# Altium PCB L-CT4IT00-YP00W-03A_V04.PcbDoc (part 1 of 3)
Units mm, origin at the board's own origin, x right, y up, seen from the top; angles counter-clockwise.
Board outline 52 x 31.8 mm, 4 copper layers (Top Layer, Layer 1, Layer 2, Bottom Layer), stack 1.288 mm thick; 160 components, 112 nets, 631 pads, 1087 vias.
Unrouted connection lines stored in the file: 130.
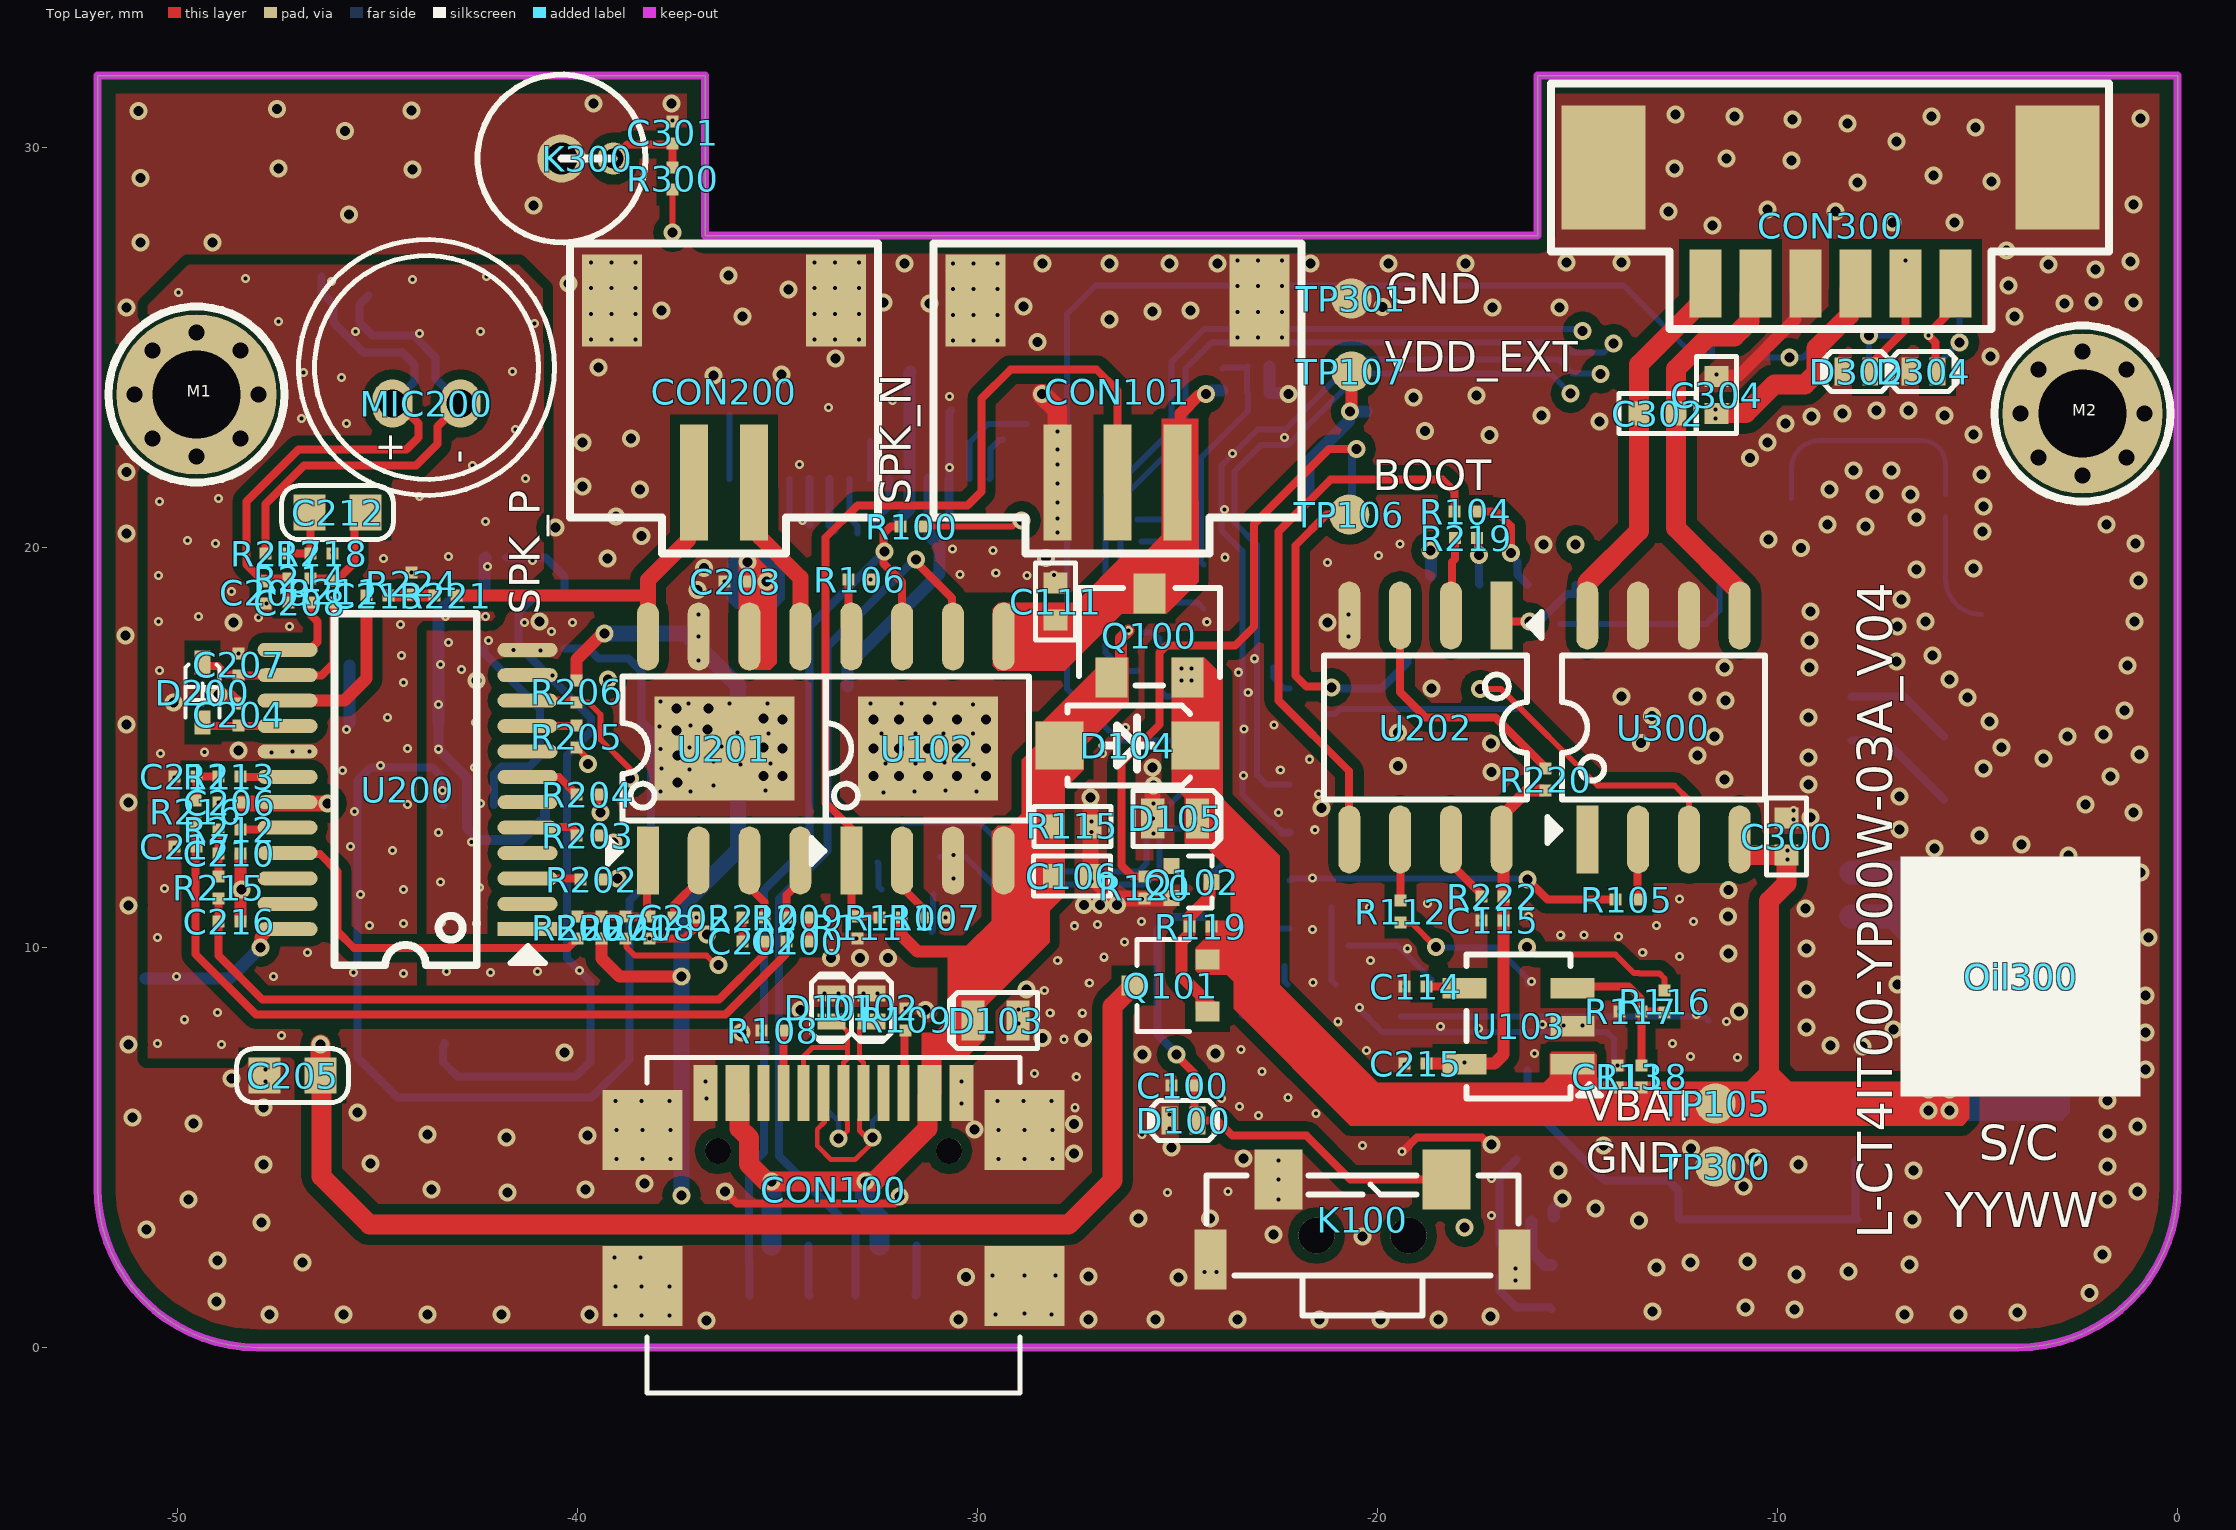
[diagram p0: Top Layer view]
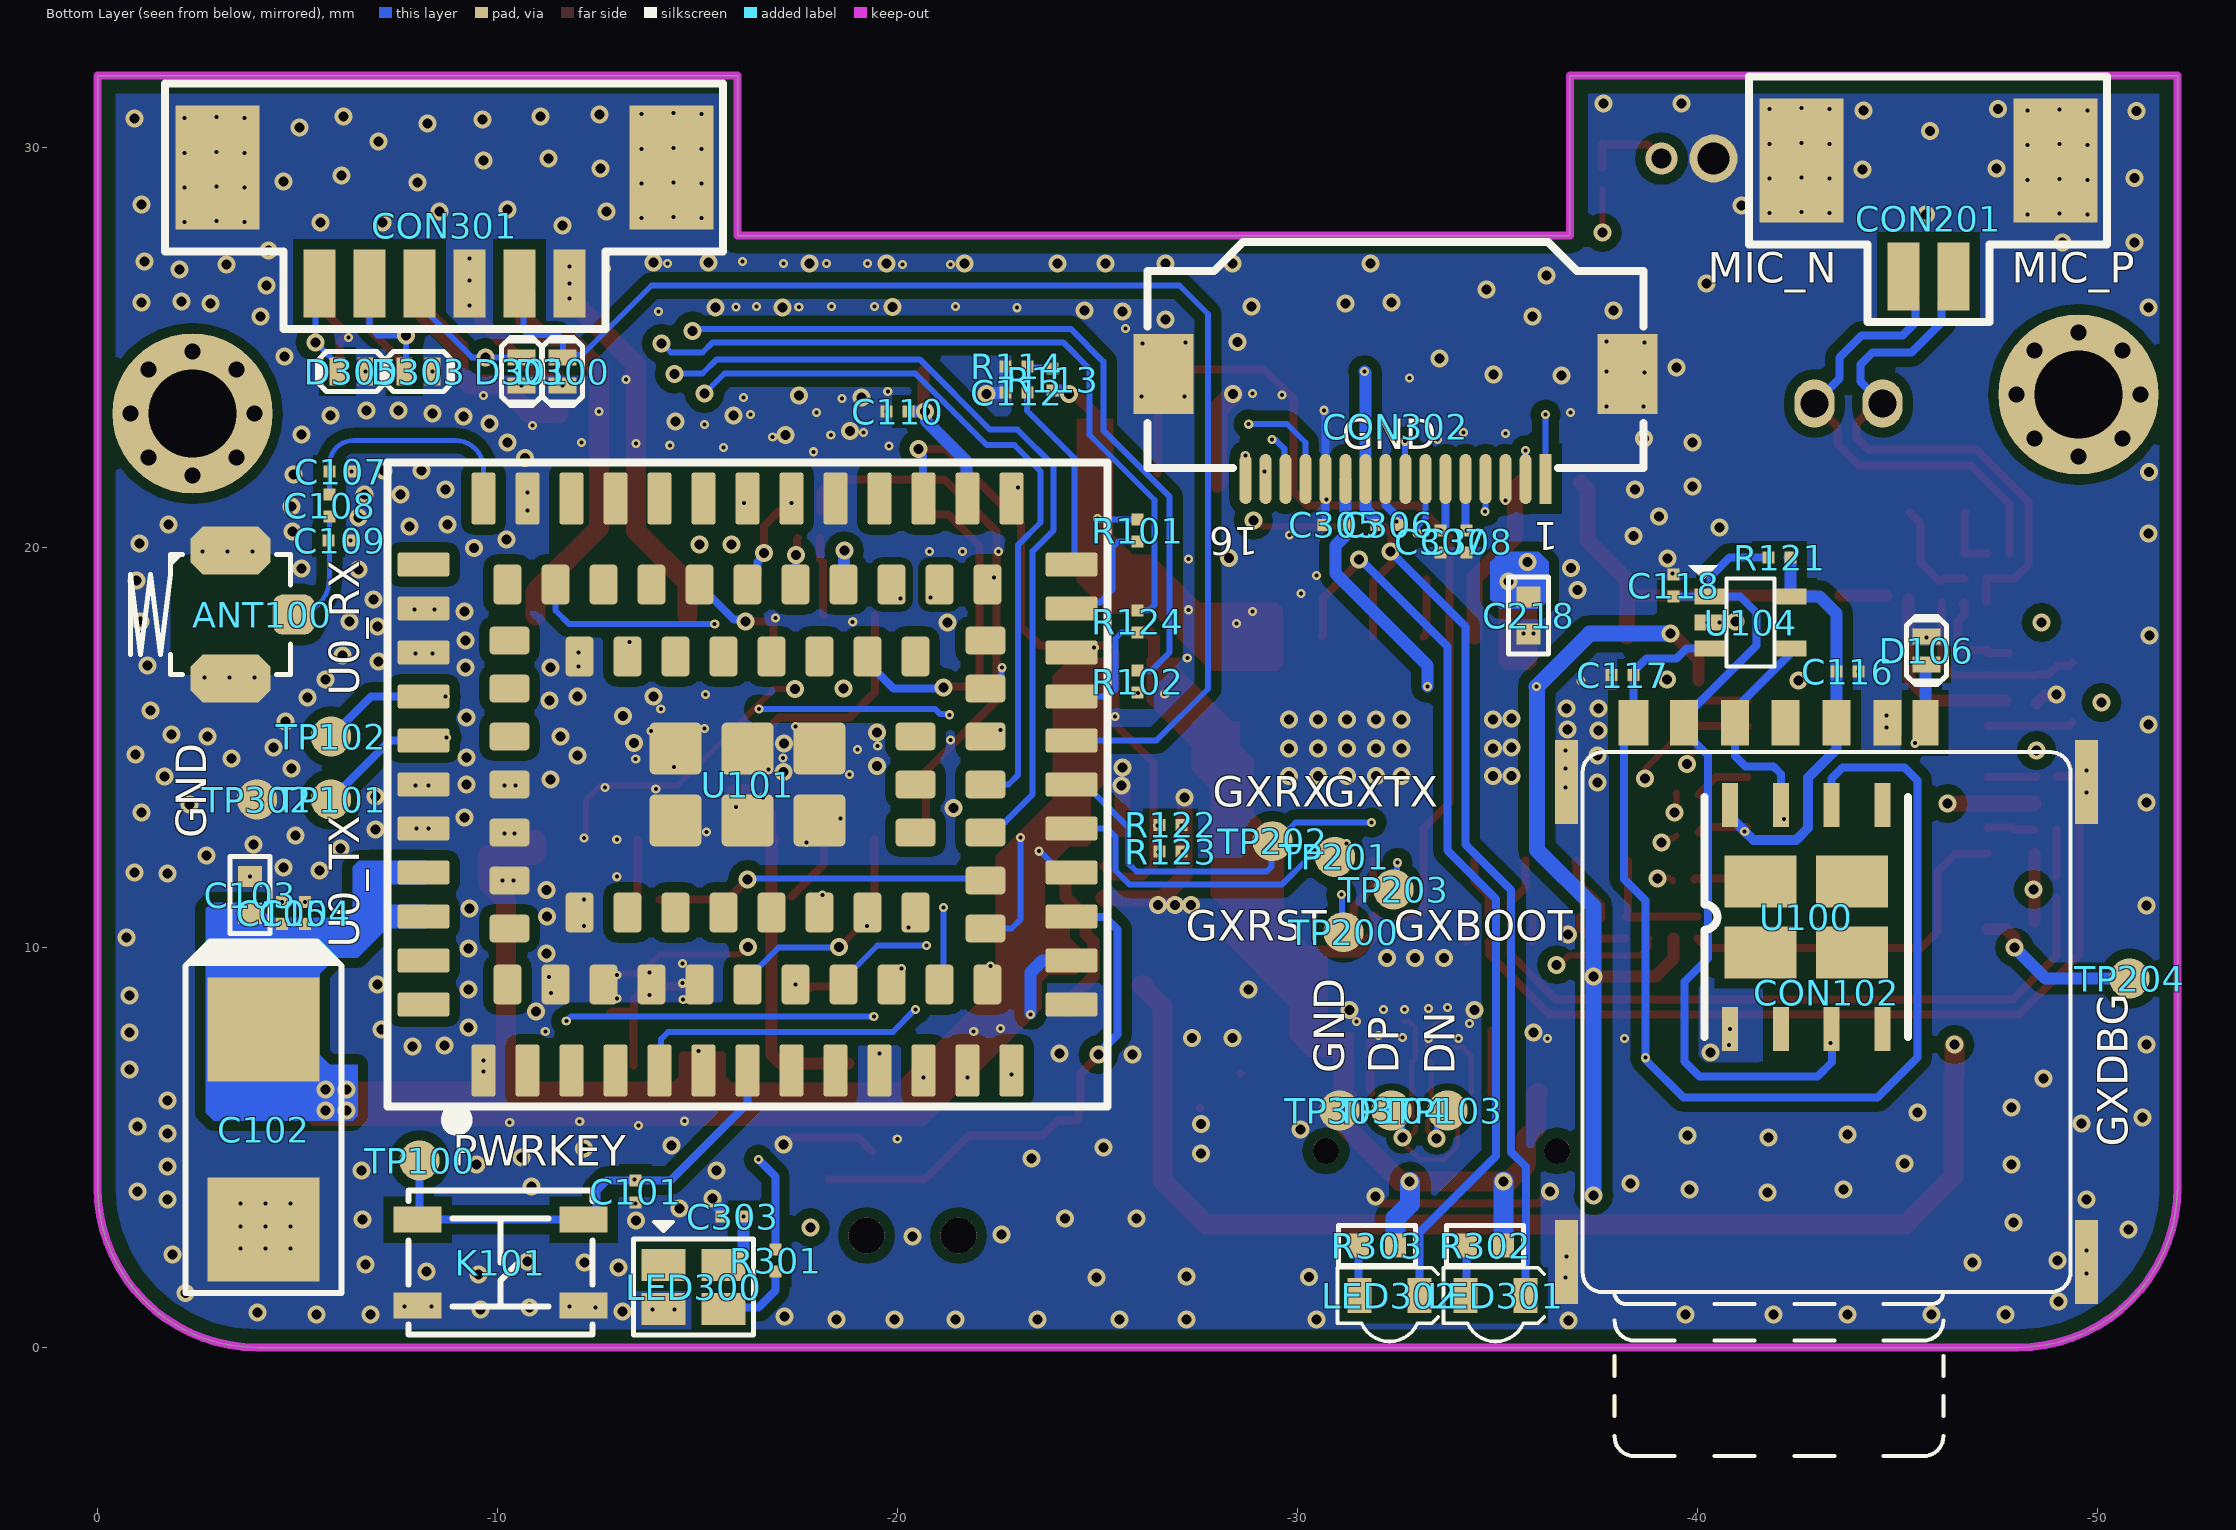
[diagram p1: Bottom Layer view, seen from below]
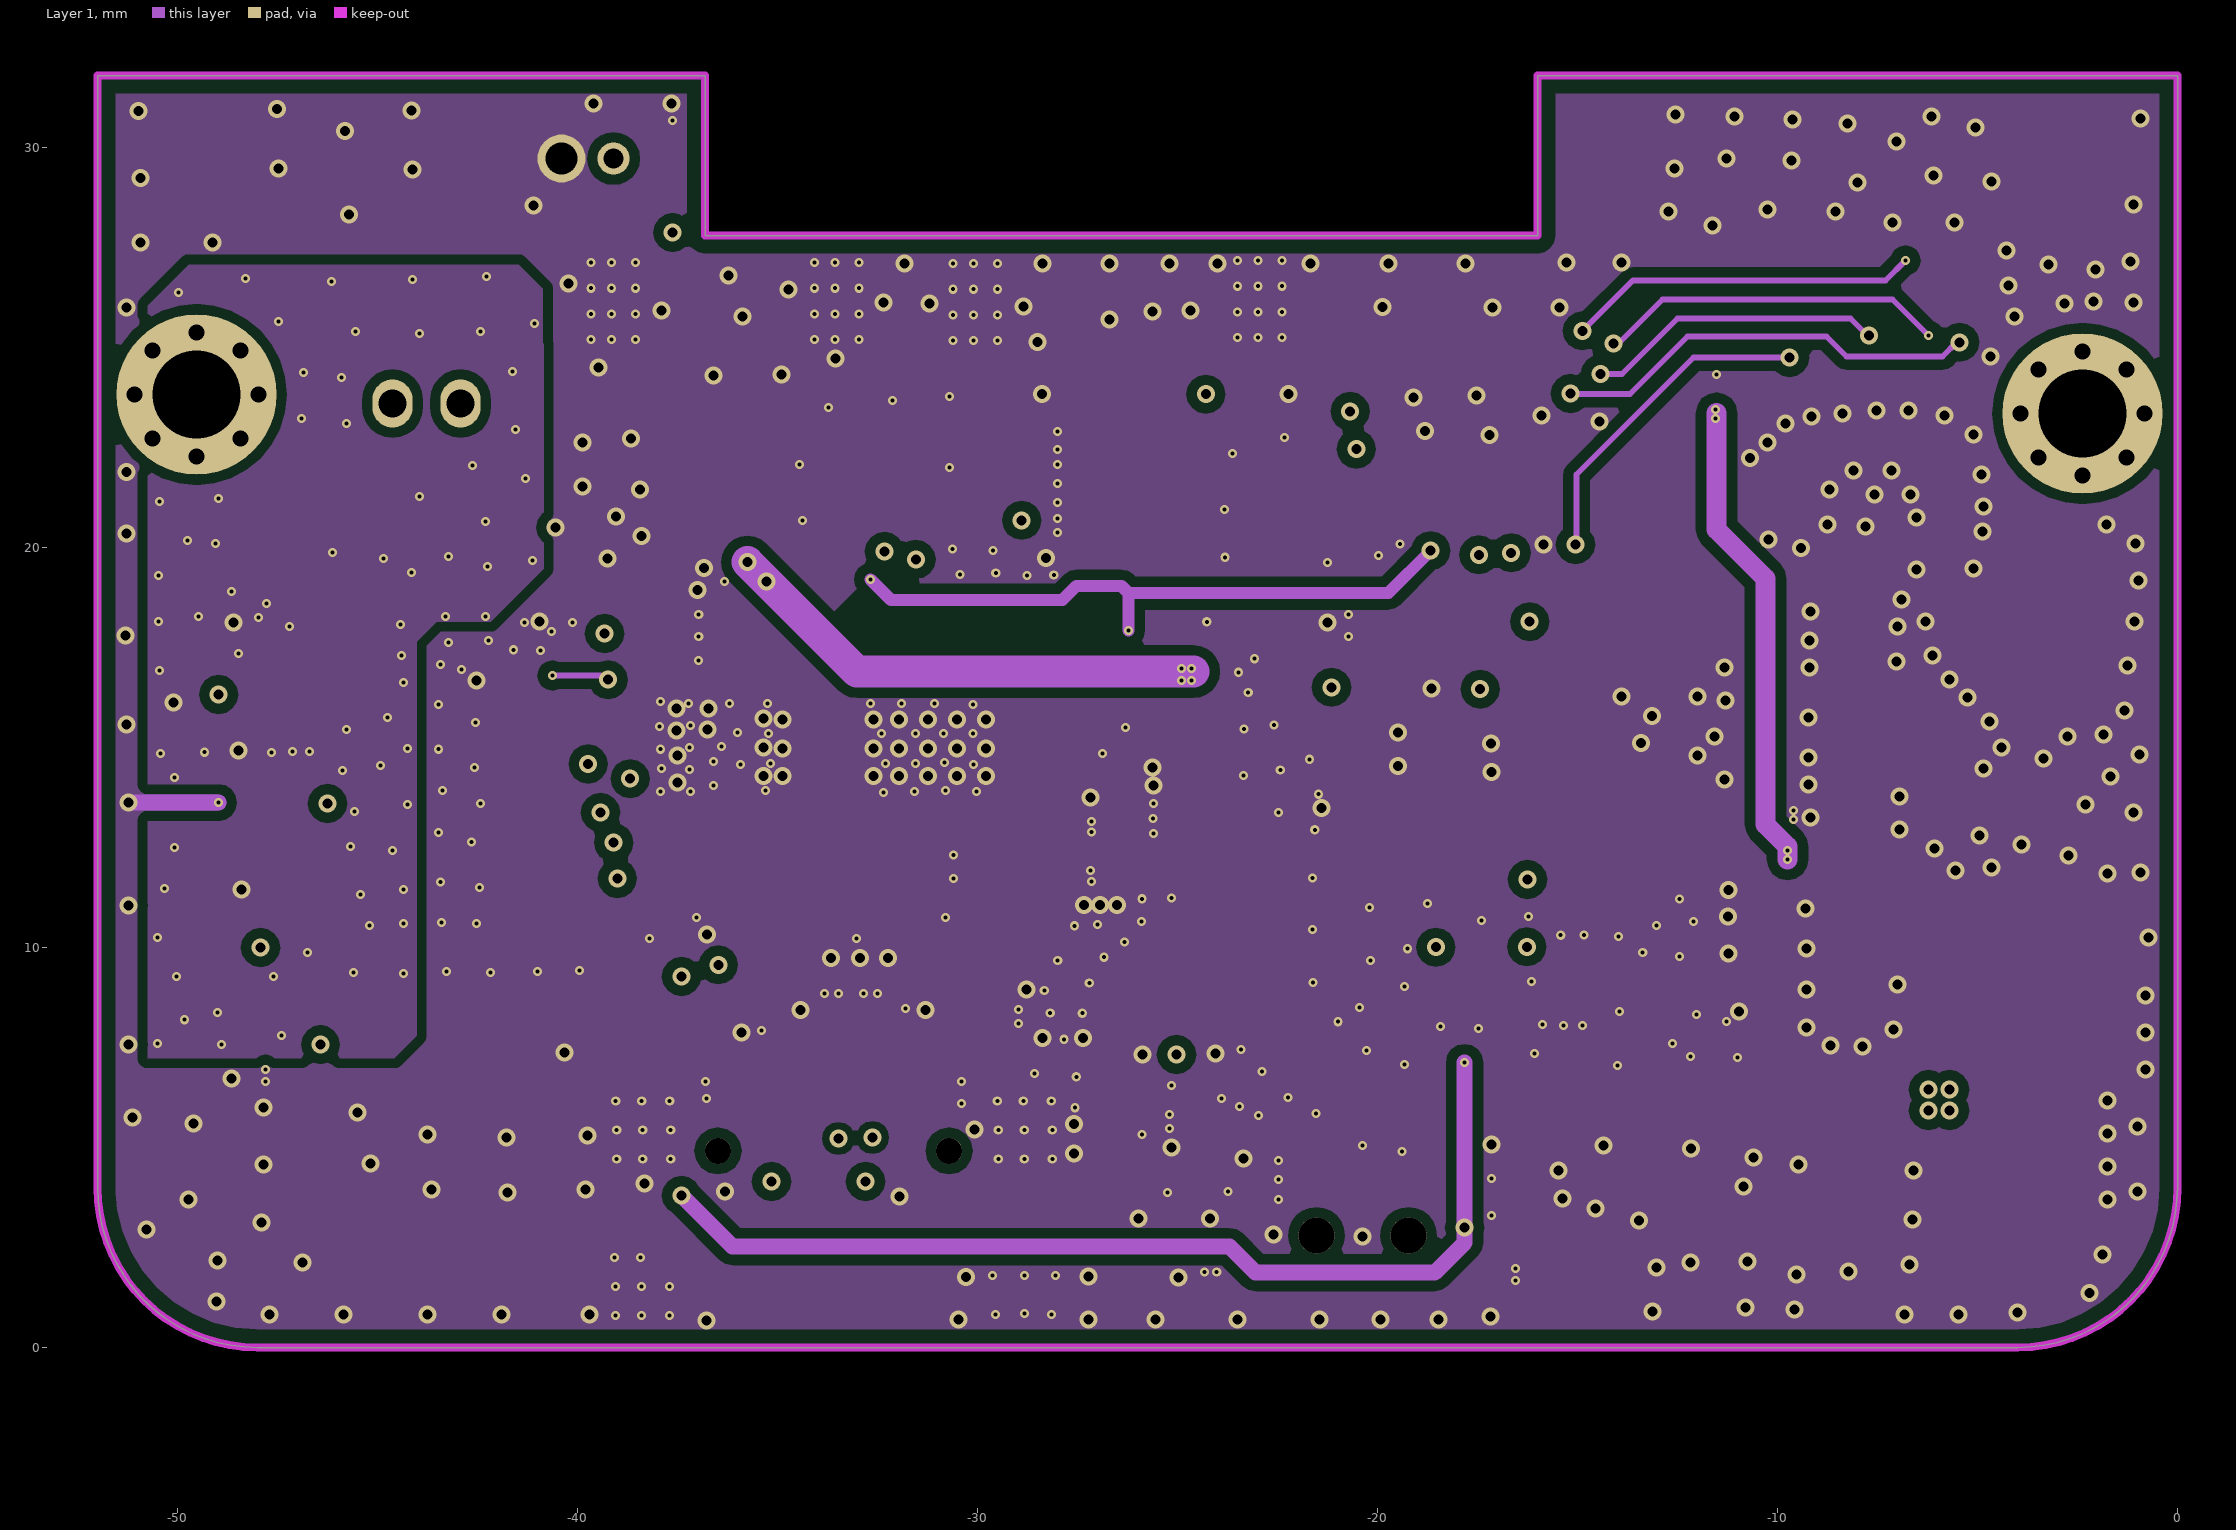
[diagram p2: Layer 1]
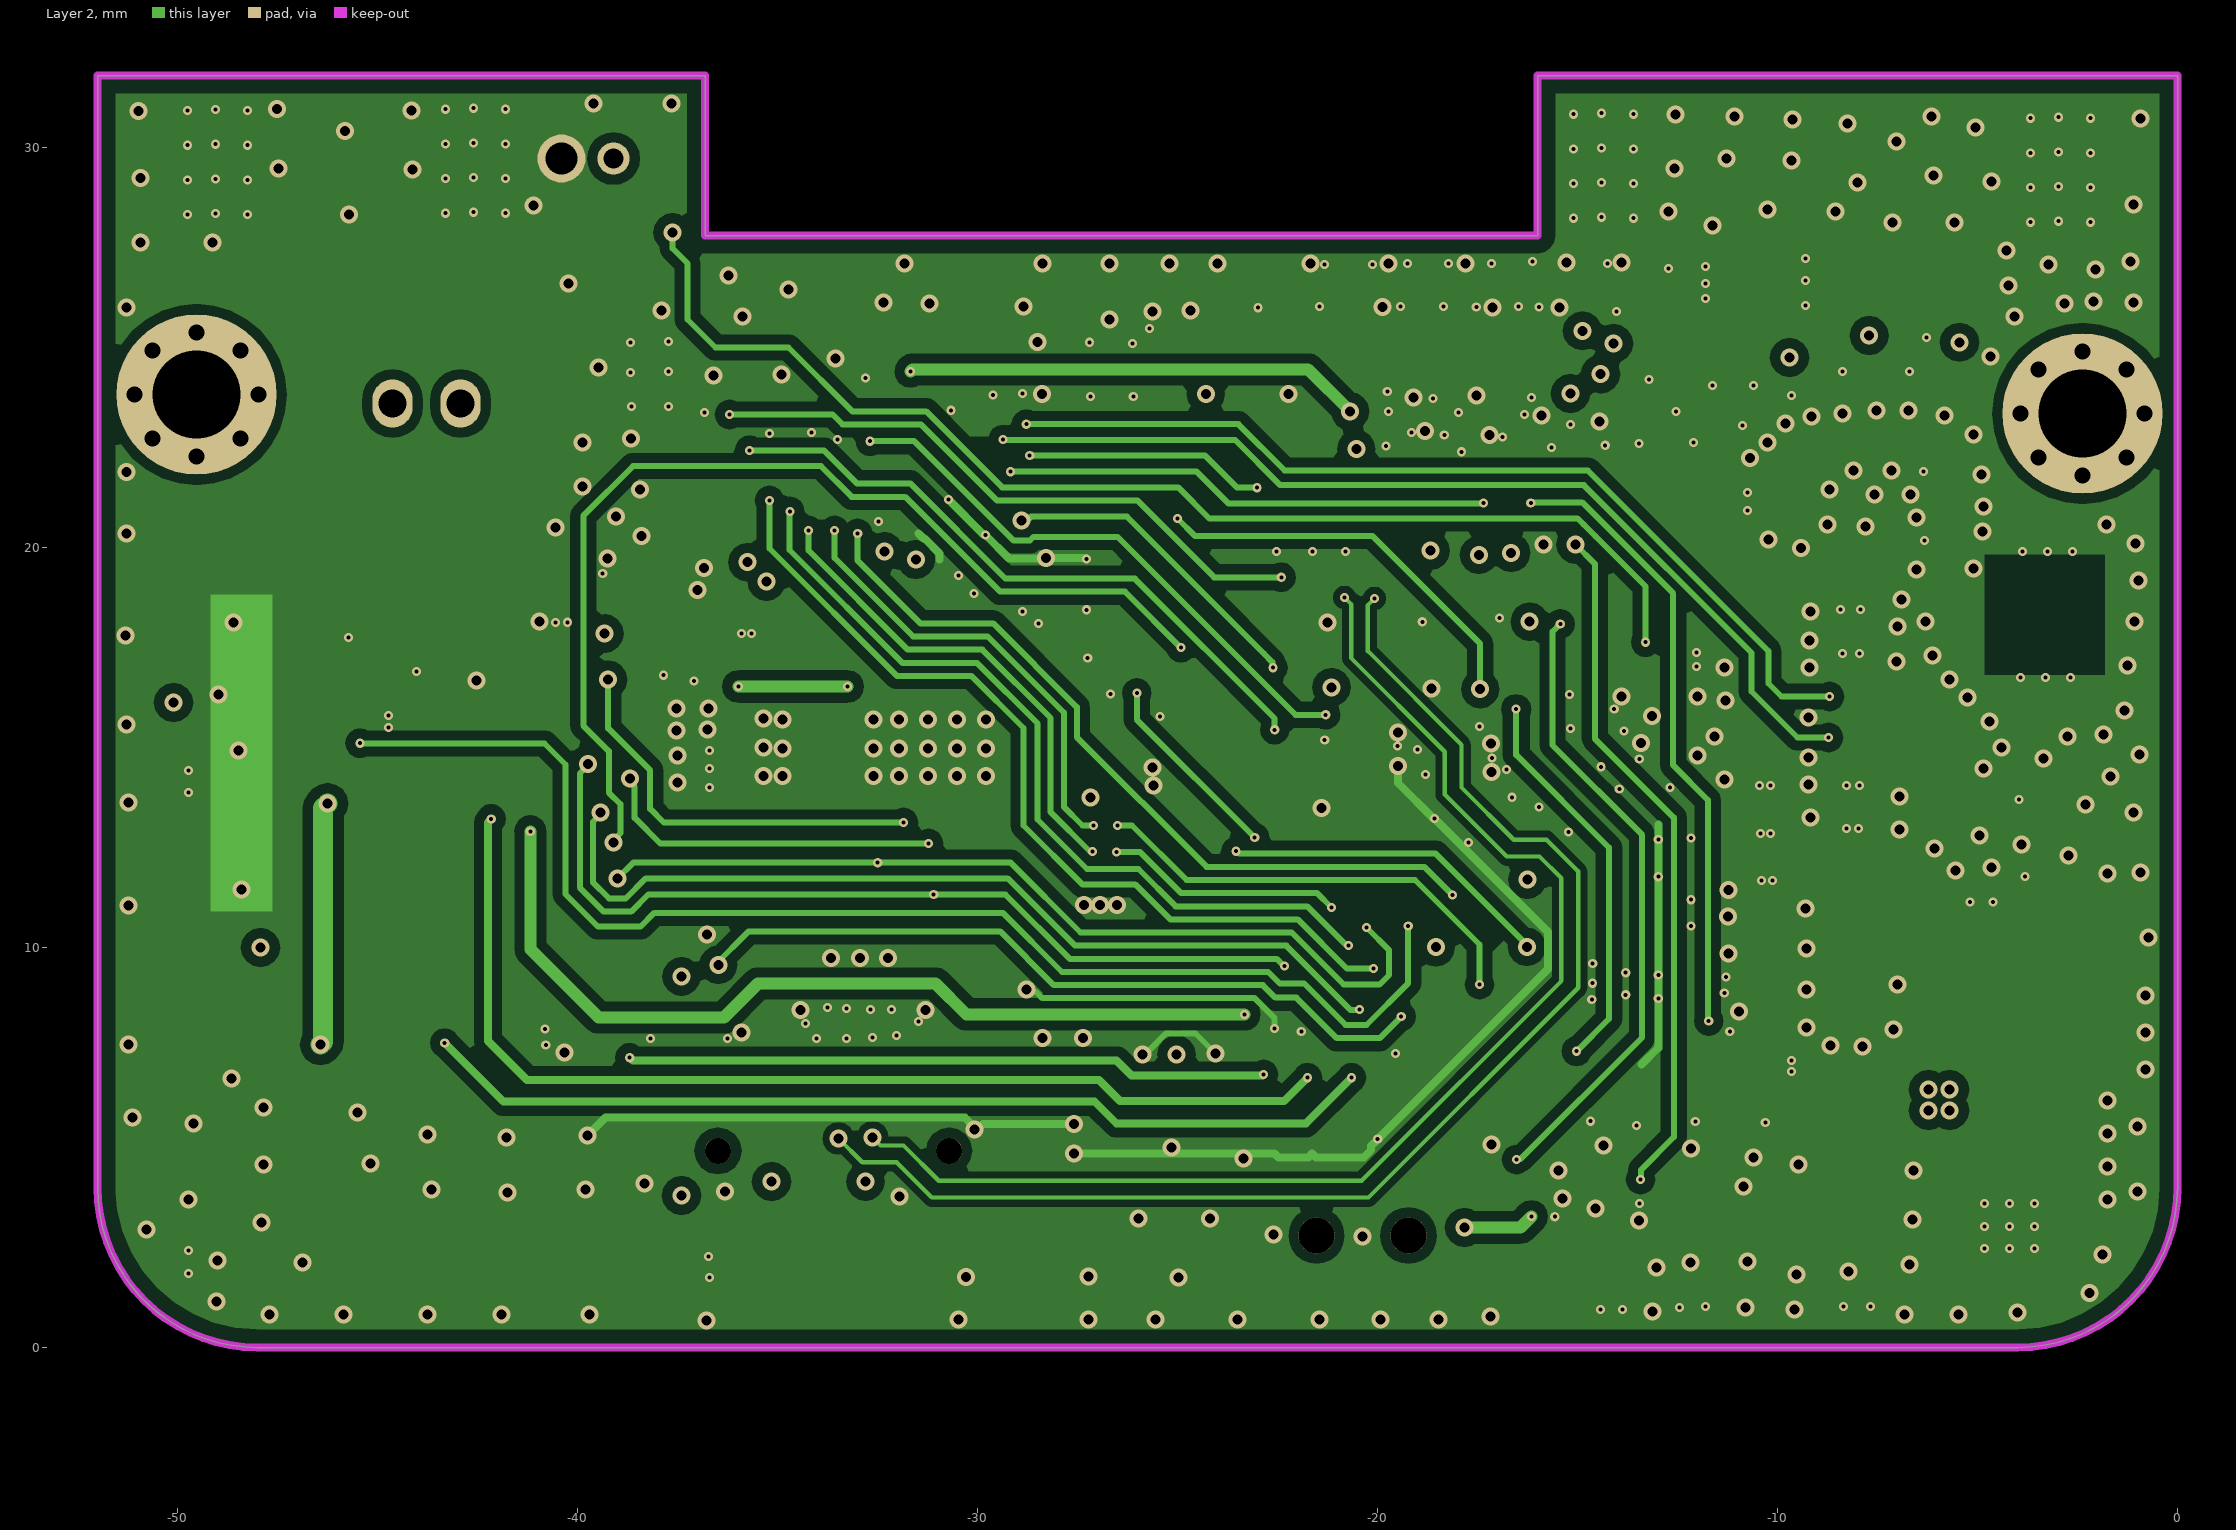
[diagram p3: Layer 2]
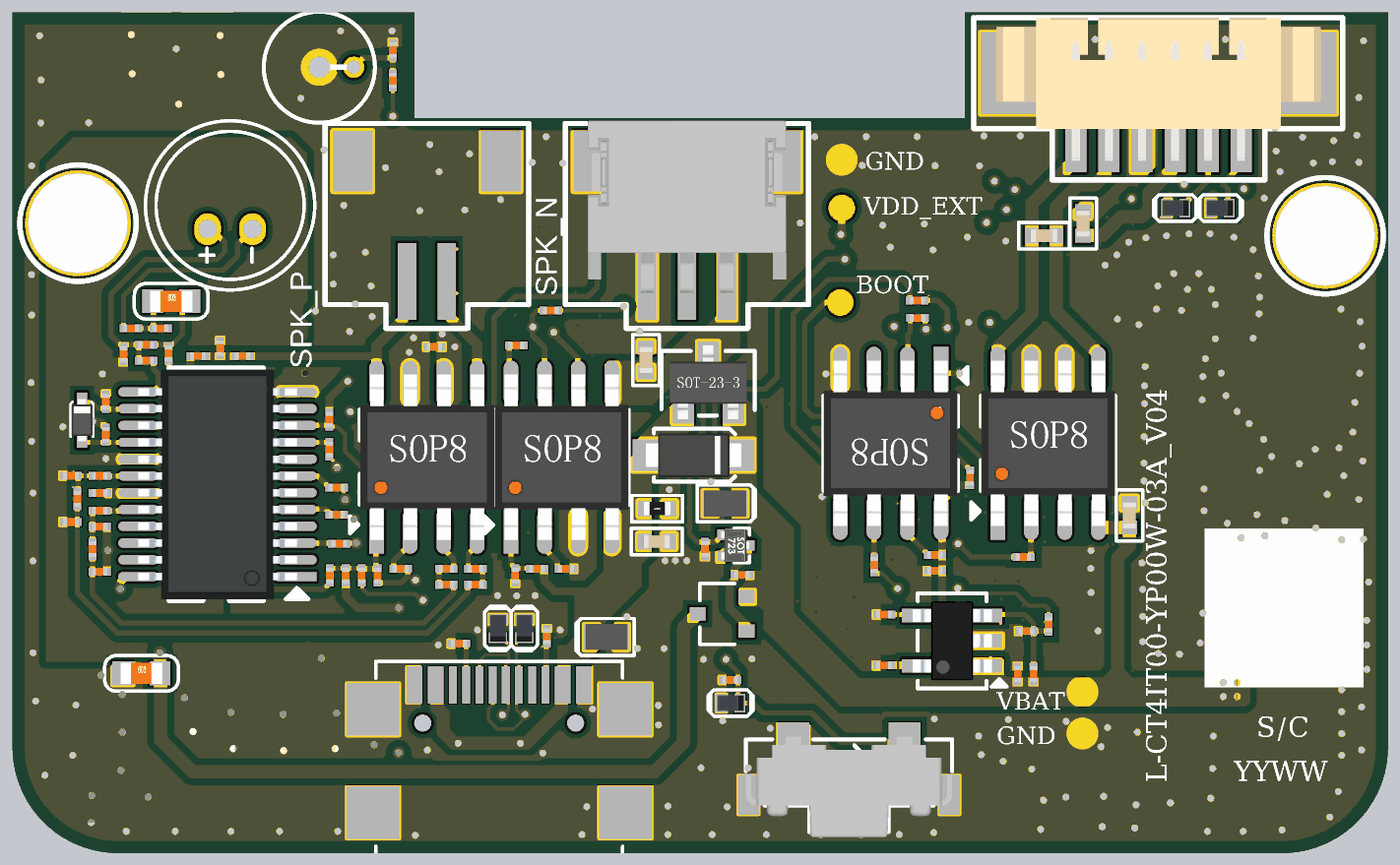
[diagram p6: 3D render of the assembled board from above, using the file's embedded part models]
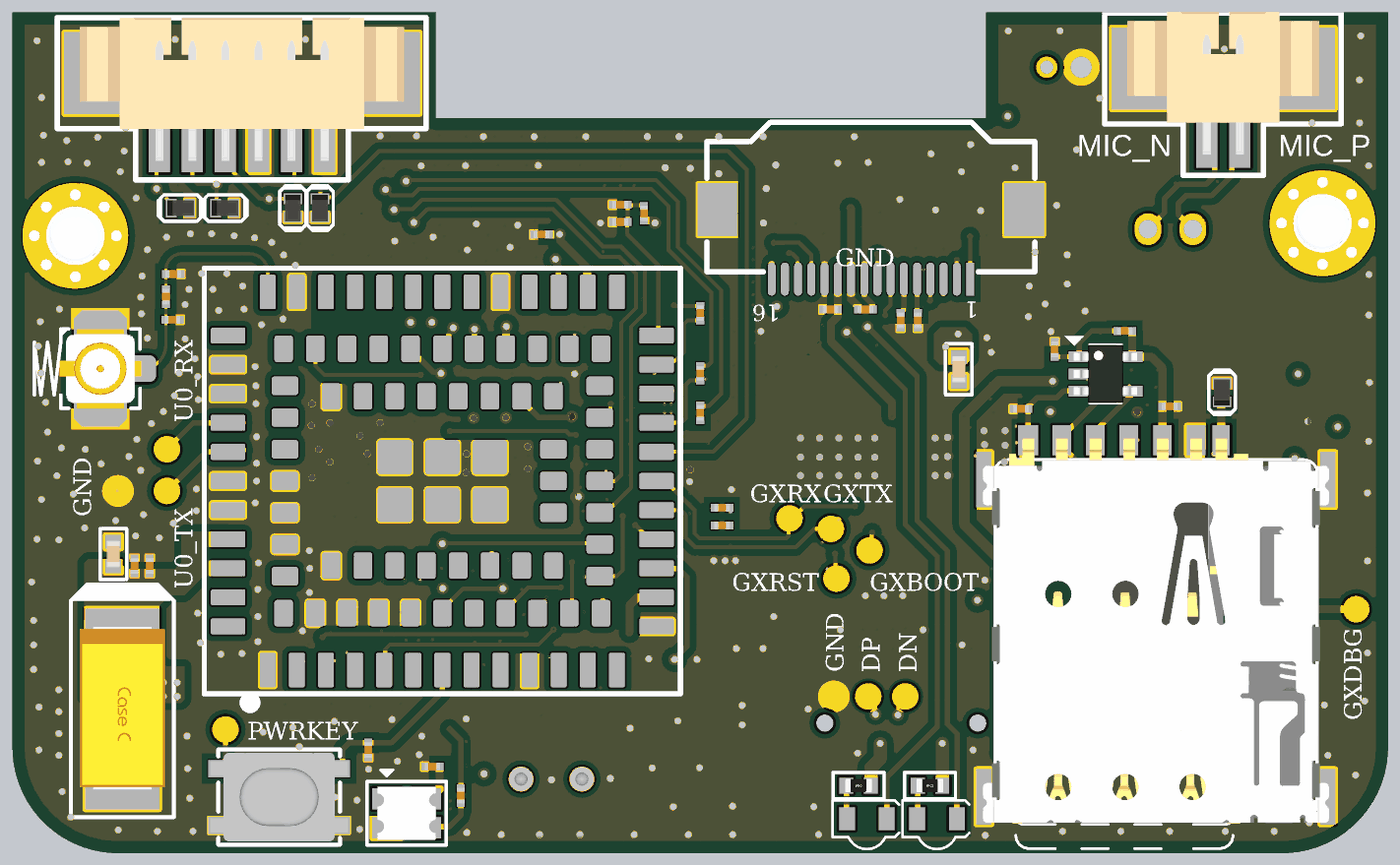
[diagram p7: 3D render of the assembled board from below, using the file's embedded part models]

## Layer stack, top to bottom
Top Solder: solder mask 0.0254, SM-001, Dk 4
Top Layer: signal copper 0.035
Dielectric 2: prepreg 0.1803, PP-021, Dk 4.7
Layer 1: signal copper 0.035
Dielectric 1: core 0.7874, Core-040, Dk 4.6
Layer 2: signal copper 0.035
Dielectric 3: prepreg 0.1803, PP-021, Dk 4.7
Bottom Layer: signal copper 0.035
Bottom Solder: solder mask 0.0254, SM-001, Dk 4

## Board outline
-52,4 ccw(c-48,4) -48,0 -4,0 ccw(c-4,4) 0,4 0,31.8 -16,31.8 -16,27.8 -36.811,27.8 -36.811,31.8 -52,31.8

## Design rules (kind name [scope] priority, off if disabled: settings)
Clearance [InDifferentialPair('USB_D')] p1: gap=0.178 ignorepadtopadclearanceinfootprint=FALSE
Clearance KEEPOUT [OnLayer('Keep-Out Layer')] p2: gap=0.35 ignorepadtopadclearanceinfootprint=FALSE except(0: Arc-Hole Track-Hole SMDPad-Hole THPad-Hole Via-Hole Fill-Hole Poly-Hole Region-Hole Text-Hole)
Clearance ISVIA [IsVia vs IsVia] p3: gap=0.35 ignorepadtopadclearanceinfootprint=FALSE
Clearance InPolygon [InPolygon] p4: gap=0.254 ignorepadtopadclearanceinfootprint=FALSE
Clearance ALL [All] p5: gap=0.2 ignorepadtopadclearanceinfootprint=FALSE except(0: Arc-Hole Track-Hole SMDPad-Hole THPad-Hole Via-Hole Fill-Hole Poly-Hole Region-Hole Text-Hole; 0.178: Arc-Arc Arc-Track Track-Track)
ComponentClearance [All] p1 off: gap=0 collisioncheckmode=3 verticalgap=0 showdistances=FALSE
DiffPairsRouting [All] p1: maxlimit=0.31 minlimit=0.178 mostfreqgap=0.31 toplayer_maxgap=0.178 toplayer_prefgap=0.178 toplayer_minwidth=0.12 toplayer_maxwidth=0.12 toplayer_prefwidth=0.12 midlayer1_maxgap=0.178 midlayer1_prefgap=0.178 midlayer1_minwidth=0.254 midlayer1_maxwidth=0.254 midlayer1_prefwidth=0.254 midlayer2_mingap=0.31 midlayer2_minwidth=0.11 midlayer2_maxwidth=0.11 midlayer2_prefwidth=0.11 bottomlayer_maxgap=0.178 bottomlayer_prefgap=0.178 bottomlayer_minwidth=0.12 bottomlayer_maxwidth=0.12 bottomlayer_prefwidth=0.12 maxuncoupledlength=12.7
HoleSize [All] p1: absolutevalues=TRUE maxlimit=10 minlimit=0.025 maxpercent=80.000 minpercent=20.000
HoleToHoleClearance [All] p1: gap=0 allowstackedmicrovias=TRUE
MinimumSolderMaskSliver [All] p1: minsoldermaskwidth=0
PolygonConnect VIA [IsVia] p1: connectstyle=Direct reliefconductorwidth=0.254 reliefentries=4 polygonreliefangle="90 Angle" airgapwidth=0.254
PolygonConnect [All] p2: connectstyle=Direct reliefconductorwidth=0.35 reliefentries=4 polygonreliefangle="90 Angle" airgapwidth=0.35
RoutingVias [All] p1: holewidth=0.3 width=0.5 viastyle="Through Hole" minholewidth=0.1 minwidth=0.23 maxholewidth=1 maxwidth=2
ShortCircuit ShortCircuit_1 [InComponent('R222') vs InNet('GND')] p1: allowed=TRUE
ShortCircuit [All] p2: allowed=FALSE
SilkToSilkClearance [All] p1: silktosilkclearance=0
SilkToSolderMaskClearance [IsPad] p1: minsilkscreentomaskgap=0 clearancetoexposedcopper=TRUE
SolderMaskExpansion [All] p1: expansion=0.102 istentingtop=FALSE
SupplyNets "Schematic Supply Nets_7" [InNet('VBUS')] p1: voltage=0.000
SupplyNets "Schematic Supply Nets_6" [InNet('VBAT_Li')] p2: voltage=0.000
SupplyNets "Schematic Supply Nets_5" [InNet('3.3V')] p3: voltage=0.000
SupplyNets "Schematic Supply Nets_4" [InNet('VCC5V')] p4: voltage=0.000
SupplyNets "Schematic Supply Nets_3" [InNet('VBAT')] p5: voltage=0.000
SupplyNets "Schematic Supply Nets_2" [InNet('VDD_EXT')] p6: voltage=0.000
SupplyNets "Schematic Supply Nets_1" [InNet('GND')] p7: voltage=0.000
SupplyNets "Schematic Supply Nets" [InNet('AGND')] p8: voltage=0.000
UnRoutedNet [All] p1: checkbadconnections=TRUE
Width [All] p1: maxlimit=5 minlimit=0.1 preferedwidth=0.2 minimp=50.000000 maximp=50.000000 favimp=50.000000
21 further rules are at their usual default settings.

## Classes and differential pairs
component class 03_Driver&Interface: C300 C301 C302 C303 C304 C305 C306 C307 C308 CON300 CON301 CON302 D300 D301 D302 D303 D304 D305 K300 LED300 LED301 LED302 M1 M2 Oil300 R300 R301 R302 R303 TP300 TP301 TP302 TP303 U300
component class 02_GX8006: C200 C201 C202 C203 C204 C205 C206 C207 C208 C209 C210 C211 C212 C213 C215 C216 C217 C218 CON200 CON201 D200 MIC200 R200 R201 R202 R203 R204 R205 R206 R207 R208 R209 R210 R211 R212 R213 R214 R215 R216 R217 R218 R219 R220 R221 R222 R224 TP200 TP201 TP202 TP203 TP204 U200 U201 U202
component class 01_NT26F6D0: ANT100 C100 C101 C102 C103 C104 C105 C106 C107 C108 C109 C110 C111 C112 C113 C114 C115 C116 C117 C118 CON100 CON101 CON102 D100 D101 D102 D103 D104 D105 D106 K100 K101 Q100 Q101 Q102 R100 R101 R102 R104 R105 R106 R107 R108 R109 R110 R111 R112 R113 R114 R115 R116 R117 R118 R119 R120 R121 R122 R123 R124 TP100 TP101 TP102 TP103 TP104 TP105 TP106 TP107 U100 U101 U102 U103 U104
differential pair USB_D: +USB_D_P -USB_D_N

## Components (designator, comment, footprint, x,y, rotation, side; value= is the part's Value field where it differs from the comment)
ANT100 "IPEX-1" IPX_U.FL-R-SMT-1 -3.325,18.325 r0 bottom locked
C100 "1uF/10V" 0201_0.25D -24.875,6.55 r0 top
C101 "1uF/10V" 0201_0.25D -13.45,3.9 r90 bottom
C102 "220uF/C型" 6032-TC -4.15,5.45 r90 bottom
C103 "10uF/10V" 0402C_0.4D -3.813,11.312 r270 bottom
C104 "0.1uF/10V" 0201_0.25D -5.188,10.863 r270 bottom
C105 "33pF" 0201_0.25D -4.613,10.863 r270 bottom
C106 "10uF/10V" 0402C_0.4D -27.641,11.787 r180 top
C107 "NC" 0201_0.25D -6.075,21.9 r0 bottom
C108 "100pF" 0201_0.25D -5.8,21.05 r90 bottom
C109 "NC" 0201_0.25D -6.05,20.175 r0 bottom
C110 "1uF/10V" 0201_0.25D -20,23.4 r180 bottom
C111 "10uF/10V" 0402C_0.4D -28.05,18.65 r270 top
C112 "NC/0.1uF/10V" 0201_0.25D -22.975,23.875 r180 bottom
C113 "1uF/10V" 0201_0.25D -14,6.775 r270 top
C114 "10nF" 0201_0.25D -19.05,9.025 r0 top
C115 "1uF/6.3V" 0201_0.25D -17.125,10.675 r0 top
C116 "1uF/6.3V" 0201_0.25D -43.75,16.9 r0 bottom
C117 "33pF" 0201_0.25D -38.125,16.807 r180 bottom
C118 "33pF" 0201_0.25D -39.4,19.05 r270 bottom
C200 "0.47uF" 0201_0.25D -34.5,10.15 r0 top
C201 "0.47uF" 0201_0.25D -35.6,10.15 r180 top
C202 "1uF/10V" 0201_0.25D -37.325,10.75 r180 top
C203 "0.1uF/10V" 0201_0.25D -36.05,19.15 r0 top
C204 "1uF/6.3V" 0201_0.25D -48.475,15.825 r270 top
C205 "22uF/10V" 0603C_0.6D -47.125,6.8 r0 top
C206 "1uF/10V" 0201_0.25D -48.7,13.625 r0 top
C207 "1uF/6.3V" 0201_0.25D -48.475,17.075 r270 top
C208 "1uF/10V" 0201_0.25D -46.95,18.625 r0 top
C209 "NC/470pF" 0201_0.25D -47.8,18.875 r270 top
C210 "1nF/10V" 0201_0.25D -48.704,12.346 r0 top
C211 "1nF/10V" 0201_0.25D -49.8,14.275 r180 top
C212 "22uF/10V" 0603C_0.6D -46,20.875 r0 top
C213 "1uF/10V" 0201_0.25D -45,18.8 r180 top
C215 "0.1uF/6.3V" 0201_0.25D -19.05,7.1 r0 top
C216 "1nF/10V" 0201_0.25D -48.704,10.646 r180 top
C217 "1nF/10V" 0201_0.25D -49.8,12.525 r180 top
C218 "10uF/10V" 0402C_0.4D -35.775,18.3 r270 bottom
C300 "4.7uF/10V" 0402C_0.4D -9.775,12.775 r270 top
C301 "NC" 0201_0.25D -37.625,30.375 r270 top
C302 "0.1uF/50V" 0402C_0.4D -13,23.35 r180 top
C303 "1uF/6.3V" 0201_0.25D -15.875,3.275 r0 bottom
C304 "4.7uF/10V" 0402C_0.4D -11.525,23.812 r270 top
C305 "1uF/6.3V" 0201_0.25D -30.925,20.563 r0 bottom
C306 "1uF/6.3V" 0201_0.25D -32.25,20.563 r180 bottom
C307 "NC" 0201_0.25D -33.575,20.15 r90 bottom
C308 "NC" 0201_0.25D -34.225,20.15 r90 bottom
CON100 "USB-TYPE C-12P" "TYPEC _6PIN板" -33.6,3.95 r0 top locked
CON101 "11-0672003-33C" SMD-1.5-3P -26.5,23.75 r180 top locked
CON102 "MUP-C7801-22" SIM-MUP-C7801 -43.225,8.875 r180 bottom locked
CON200 "11-0672002-33C" SMD-1.5-2P -36.335,23.75 r180 top locked
CON201 "11-0702002-331" SMD-1.25-2P -45.775,28.225 r0 bottom
CON300 "FPC-6" SMD-1.25-6P -8.675,29.5 r180 top locked
CON301 "FPC-6" SMD-1.25-6P -8.675,29.5 r0 bottom locked
CON302 "FPC-16" FPC0.5E-16P -32.45,23.025 r0 bottom locked
D100 "TVS" DFN1006-NP#1 -24.85,5.675 r180 top
D101 "WS6183KF" DFN1006-NP#1 -33.65,8.496 r90 top
D102 "WS6183KF" DFN1006-NP#1 -32.65,8.496 r90 top
D103 "DIODE-TVS" UDFN2(1610) -29.55,8.175 r0 top
D104 "DIODE" SOD-123-FL -26.25,15.05 r180 top
D105 "WS4.5DPVL" UDFN2(1610) -25.061,13.226 r180 top
D106 "TVS" DFN1006-NP#2 -45.725,17.425 r90 bottom
D200 "DIODE" SOD-523 -49.375,16.375 r270 top
D300 "TVS" DFN1006-NP#2 -11.625,24.4 r270 bottom
D301 "TVS" DFN1006-NP#2 -10.6,24.4 r270 bottom
D302 "TVS" DFN1006-NP#1 -8.025,24.4 r180 top
D303 "TVS" DFN1006-NP#2 -8.025,24.4 r180 bottom
D304 "TVS" DFN1006-NP#1 -6.35,24.4 r180 top
D305 "TVS" DFN1006-NP#2 -6.35,24.4 r180 bottom
K100 "1414000783" SW-7.8X3.5-4P-HOLE-S-2 -20.375,3.2 r0 top
K101 "BUTTON-4" SW-4.2X3.2-4P-S -10.08,2.12 r0 bottom
K300 "NC" SW-18020 -40.4,29.725 r90 top
LED300 "RGB" D2018-RGB -14.9,1.509 r180 bottom
LED301 "红" LED-W-0603-3 -34.95,1.3 r0 bottom
LED302 "绿" LED-W-0603-3 -32.3,1.3 r0 bottom
M1 "MARK" HOLD_2mm_4mm -49.525,23.825 r0 top
M2 "MARK" HOLD_2mm_4mm -2.375,23.35 r0 top locked
MIC200 "NC" MIC-CXM6022P423C1033 -43.775,24.5 r90 top locked
Oil300 "Oil" "White oil-6X6" -3.925,9.275 r0 top
Q100 "P-MOS-D1" SOT-23-3G -25.703,17.8 r270 top
Q101 "P-MOS-D1" SOT-323-3G -25.175,9.05 r0 top
Q102 "N-MOS-D" SOT-723-3G -24.65,11.636 r180 top
R100 "1K" 0201_0.25D -31.65,20.525 r180 top
R101 "0R" 0201_0.25D -26,20.425 r90 bottom
R102 "0R" 0201_0.25D -26,16.65 r90 bottom
R104 "33R" 0201_0.25D -17.8,20.9 r180 top
R105 "0R" 0201_0.25D -13.775,11.2 r0 top
R106 "100K" 0201_0.25D -32.95,19.2 r0 top
R107 "1.2K/1%" 0201_0.25D -31.075,10.75 r0 top
R108 "5.1K" 0201_0.25D -35.125,7.925 r180 top
R109 "5.1K" 0201_0.25D -31.8,8.2 r90 top
R110 "4.7K/1%" 0201_0.25D -32.175,10.75 r180 top
R111 "51K/1%" 0201_0.25D -32.995,10.5 r270 top
R112 "33R" 0201_0.25D -19.425,10.9 r90 top
R113 "NC/47K/1%" 0201_0.25D -23.875,24.2 r270 bottom
R114 "NC/47K/1%" 0201_0.25D -22.975,24.525 r180 bottom
R115 "470K" 0402R_0.4D -27.626,13.026 r180 top
R116 "4.7K" 0201_0.25D -12.825,8.65 r270 top
R117 "47K" 0201_0.25D -13.675,8.4 r0 top
R118 "NC" 0201_0.25D -13.4,6.775 r90 top
R119 "100K" 0201_0.25D -24.425,10.525 r180 top
R120 "10K" 0201_0.25D -25.825,11.5 r90 top
R121 "NC" 0201_0.25D -42.05,19.75 r180 bottom
R122 "22R" 0201_0.25D -26.825,13.067 r0 bottom
R123 "22R" 0201_0.25D -26.825,12.396 r0 bottom
R124 "0R" 0201_0.25D -26,18.15 r270 bottom
R200 "0R" 0201_0.25D -40,10.5 r270 top
R201 "NC" 0201_0.25D -38.8,10.5 r90 top
R202 "1K" 0201_0.25D -39.65,11.7 r180 top
R203 "1K" 0201_0.25D -39.75,12.8 r180 top
R204 "1K" 0201_0.25D -39.75,13.825 r180 top
R205 "1K" 0201_0.25D -40.025,15.275 r90 top
R206 "1K" 0201_0.25D -40.025,16.4 r90 top
R207 "NC" 0201_0.25D -39.4,10.5 r270 top
R208 "100K" 0201_0.25D -38.2,10.5 r90 top
R209 "150K/1%" 0201_0.25D -34.5,10.75 r180 top
R210 "150K/1%" 0201_0.25D -35.6,10.75 r0 top
R211 "510R" 0201_0.25D -46.1,18.9 r270 top
R212 "10K" 0201_0.25D -48.704,12.946 r0 top
R213 "10K" 0201_0.25D -48.704,14.271 r0 top
R214 "1K" 0201_0.25D -46.95,19.225 r180 top
R215 "10K" 0201_0.25D -48.975,11.5 r270 top
R216 "10K" 0201_0.25D -49.55,13.4 r90 top
R217 "0R" 0201_0.25D -47.525,19.85 r180 top
R218 "510R" 0201_0.25D -46.4,19.85 r180 top
R219 "33R" 0201_0.25D -17.788,20.238 r180 top
R220 "4.7K" 0201_0.25D -15.8,14.2 r90 top
R221 "2K" 0201_0.25D -43.3,18.8 r180 top
R222 "4.7K" 0201_0.25D -17.125,11.275 r0 top
R224 "2K" 0201_0.25D -44.15,19.1 r90 top
R300 "0R" 0201_0.25D -37.625,29.225 r90 top
R301 "0R" 0201_0.25D -16.95,2.175 r90 bottom
R302 "1K" 0402R_0.4D -34.687,2.55 r180 bottom
R303 "1K" 0402R_0.4D -31.988,2.55 r0 bottom
TP100 "PWRKEY" test -8.05,4.675 r270 bottom
TP101 "U0_TX" test -5.838,13.7 r0 bottom
TP102 "U0_RX" test -5.838,15.275 r0 bottom
TP103 "USB_DN" test -33.75,5.925 r180 bottom
TP104 "USB_DP" test -32.35,5.925 r180 bottom
TP105 "VBAT" test -11.55,6.1 r180 top
TP106 "BOOT" test -20.705,20.825 r90 top
TP107 "VDD_EXT" test -20.651,24.4 r180 top
TP200 "GX_RST" test -31.15,10.384 r0 bottom
TP201 "GX_TX" test -30.937,12.263 r180 bottom
TP202 "GX_RX" test -29.375,12.658 r180 bottom
TP203 "GX_BOOT" test -32.4,11.45 r0 bottom
TP204 "GX_DBG" test -50.8,9.225 r180 bottom
TP300 "GND" test -11.55,4.525 r90 top
TP301 "GND" test -20.651,26.225 r270 top
TP302 "GND" test -3.988,13.7 r90 bottom
TP303 "GND" test -31.05,5.925 r180 bottom
U100 "" DFN8(1.27)-6X5 -42.718,10.761 r90 bottom locked
U101 "NT26F6D0" "NT26-FCN B" -16.25,14.075 r90 bottom locked
U102 "CL4056D" SOP-8(1.27)-GND -31.25,14.975 r0 top
U103 "SGM2036-XYN5G/TR" SOT-23-5P -16.475,8.035 r0 top
U104 "NSQA6V8AW5T2G" SOT-323-5 -41.325,18.125 r0 bottom
U200 "GX8006" SSOP-24(0.635) -44.25,13.95 r90 top locked
U201 "CST8302A" SOP-8(1.27)-GND -36.335,14.975 r0 top
U202 "NC" SOP-8(1.27) -18.8,15.5 r180 top locked
U300 "TC118S" SOP-8(1.27) -12.85,15.5 r0 top locked

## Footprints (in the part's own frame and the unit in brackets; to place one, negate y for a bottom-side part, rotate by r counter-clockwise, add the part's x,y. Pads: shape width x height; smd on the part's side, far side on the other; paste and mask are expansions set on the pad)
0201_0.25D [mm]
  rect 0.3x0.3 smd mask+0.051: 1(-0.275,0) 2(0.275,0)
  body extent -0.3,-0.15 0.3,0.15, height 0.28
0402C_0.4D [mm]
  rect 0.525x0.6 smd: 1(-0.463,0) 2(0.463,0)
  silkscreen extent -0.96,-0.5 0.96,0.5, body extent -0.5,-0.25 0.5,0.25, height 0.48
0402R_0.4D [mm]
  rect 0.525x0.6 smd: 1(-0.463,0) 2(0.463,0)
  silkscreen extent -0.96,-0.5 0.96,0.5, body extent -0.5,-0.25 0.5,0.25, height 0.36
0603C_0.6D [mm]
  rect 0.8x0.9 smd mask+0.076: 1(-0.7,0) 2(0.7,0)
  silkscreen extent -1.4,-0.68 1.4,0.67, body extent -0.8,-0.4 0.8,0.4, height 0.3
6032-TC [mm]
  rect 2.6x2.8 smd: 1(2.5,0) 2(-2.5,0)
  silkscreen extent -4.09,-1.95 4.7,1.95, body extent -3.06,-1.61 3.13,1.6, height 2.67
D2018-RGB [mm]
  rect 1.1x0.8 smd paste+0 mask+0.102: 1(-0.75,0.55) 2(-0.75,-0.55) 3(0.75,-0.55) 4(0.75,0.55)
  silkscreen extent -1.5,-1.2 1.5,1.64, body extent -1.1,-1 1.1,1, height 0.84
DFN8(1.27)-6X5 [mm]
  rect 1.3x1.8 smd: 0(-0.889,-1.143) 0(-0.889,1.143) 0(0.889,-1.143) 0(0.889,1.143)
  rect 1.1x0.4 smd: 1(-2.8,1.905) 2(-2.8,0.635) 3(-2.8,-0.635) 4(-2.8,-1.905) 5(2.8,-1.905) 6(2.8,-0.635) 7(2.8,0.635) 8(2.8,1.905)
  round 0.3 on Mech13 mask+0: ""(-2.8,1.905)
  rect 0.6x0.4 on Mech2 mask+0: ""(-2.7,-1.905) ""(-2.7,-0.635) ""(-2.7,0.635) ""(-2.7,1.905) ""(2.7,-1.905) ""(2.7,-0.635) ""(2.7,0.635) ""(2.7,1.905)
  rect 3.4x4.2 on Mech2 mask+0: ""(0,0)
  round 0.3 on Mech2 mask+0: ""(0,0) ""(0,0)
  silkscreen extent -3,-2.54 3,2.54, body extent -3.05,-2.5 3.05,2.5, height 0.95
DFN1006-NP#1 [mm]
  rect 0.4x0.7 smd mask+0.051: A(0.35,0) K(-0.35,0)
  rect 0.25x0.5 on Mech1: ""(-0.325,0) ""(0.325,0)
  silkscreen extent -0.85,-0.5 0.85,0.5, body extent -0.5,-0.3 0.5,0.3, height 0.5
DFN1006-NP#2 [mm]
  rect 0.4x0.7 smd mask+0.051: A(0.35,0) K(-0.35,0)
  rect 0.25x0.5 on Mech2: ""(-0.325,0) ""(0.325,0)
  silkscreen extent -0.85,-0.5 0.85,0.5, body extent -0.5,-0.3 0.5,0.3, height 0.5
FPC0.5E-16P [mm]
  rect 1.5x2 smd mask+0.075: 0(-5.8,-1.312) 0(5.8,-1.312)
  rect 0.3x0.95 on Mech2 mask+0.051: 0(-3.75,1.313) 0(-3.25,1.313) 0(-2.75,1.313) 0(-2.25,1.313) 0(-1.75,1.313) 0(-1.25,1.313) 0(-0.75,1.313) 0(-0.25,1.313) 0(0.25,1.313) 0(0.75,1.313) 0(1.25,1.313) 0(1.75,1.313) 0(2.25,1.313) 0(2.75,1.313) 0(3.25,1.313) 0(3.75,1.313)
  rect 0.3x1.25 smd mask+0.051: 1(-3.75,1.313)
  oval 0.3x1.25 smd mask+0.051: 2(-3.25,1.313) 3(-2.75,1.313) 4(-2.25,1.313) 5(-1.75,1.313) 6(-1.25,1.313) 7(-0.75,1.313) 8(-0.25,1.313) 9(0.25,1.313) 10(0.75,1.313) 11(1.25,1.313) 12(1.75,1.313) 13(2.25,1.313) 14(2.75,1.313) 15(3.25,1.313) 16(3.75,1.313)
  silkscreen extent -6.2,-4.61 6.2,1.04, body extent -6.2,-4.59 6.2,1.08, height 2
HOLD_2mm_4mm [mm] "固定孔"
  round 0.7 hole 0.4 paste-2539.97 mask+0.102: 1(-1.55,0) 1(-1.096,-1.096) 1(-1.096,1.096) 1(0,-1.55) 1(0,1.55) 1(1.096,-1.096) 1(1.096,1.096) 1(1.55,0)
  round 4 hole 2.2 mask+0.05: 1(0,0)
  body extent -1.9,-1.9 1.9,1.9, height 2
IPX_U.FL-R-SMT-1 [mm]
  rrect50% 1.05x1 smd: 1(-1.575,0)
  oct 2x1.2 smd: 2(0,-1.6) 3(0,1.6)
  silkscreen extent -1.5,-1.5 2.5,1.5, body extent -1.55,-1.5 1.55,1.5, height 1.25
LED-W-0603-3 [mm] "侧贴LED"
  rect 0.6x0.87 smd: A(0.75,0) K(-0.75,0)
  silkscreen extent -1.22,-0.69 1.3,1.15
MIC-CXM6022P423C1033 [mm]
  oval 1.2x1 hole 0.7: 1(-0.9,0.85) 2(-0.9,-0.85)
  silkscreen extent -3.2,-3.2 3.2,3.2, body extent -3,-3 3,3, height 1.5
"NT26-FCN B" [mm]
  rrect20% 1.3x0.6 smd mask+0.076: 1(-7.15,6.6) 2(-7.15,5.5) 3(-7.15,4.4) 4(-7.15,3.3) 5(-7.15,2.2) 6(-7.15,1.1) 7(-7.15,0) 8(-7.15,-1.1) 9(-7.15,-2.2) 10(-7.15,-3.3) 11(-7.15,-4.4) 12(-7.15,-5.5) 13(-7.15,-6.6) 23(7.15,-6.6) 24(7.15,-5.5) 25(7.15,-4.4) 26(7.15,-3.3) 27(7.15,-2.2) 28(7.15,-1.1) 29(7.15,0) 30(7.15,1.1) 31(7.15,2.2) 32(7.15,3.3) 33(7.15,4.4) 34(7.15,5.5) 35(7.15,6.6)
  rrect20% 0.6x1.3 smd mask+0.076: 14(-4.4,-8.1) 15(-3.3,-8.1) 16(-2.2,-8.1) 17(-1.1,-8.1) 18(0,-8.1) 19(1.1,-8.1) 20(2.2,-8.1) 21(3.3,-8.1) 22(4.4,-8.1) 36(4.4,8.1) 37(3.3,8.1) 38(2.2,8.1) 39(1.1,8.1) 40(0,8.1) 41(-1.1,8.1) 42(-2.2,8.1) 43(-3.3,8.1) 44(-4.4,8.1) 95(-5.5,-8.1) 96(5.5,-8.1) 97(5.5,8.1) 98(-5.5,8.1)
  rrect30% 1x0.7 smd mask+0.064: 45(-5,4.8) 46(-5,3.6) 47(-5,2.4) 48(-5,1.2) 49(-5,0) 50(-5,-1.2) 51(-5,-2.4) 52(-5,-3.6) 53(-5,-4.8) 59(5,-4.8) 60(5,-3.6) 61(5,-2.4) 62(5,-1.2) 63(5,0) 64(5,1.2) 65(5,2.4) 66(5,3.6) 67(5,4.8) 73(-3.2,4.2) 74(-3.2,3) 75(-3.2,1.8) 76(-3.2,0.6) 77(-3.2,-0.6) 78(-3.2,-1.8) 79(-3.2,-3) 80(-3.2,-4.2) 81(3.2,-4.2) 82(3.2,-3) 83(3.2,-1.8) 84(3.2,-0.6) 85(3.2,0.6) 86(3.2,1.8) 87(3.2,3) 88(3.2,4.2) 99(-5,6) 100(-5,-6) 103(5,-6) 104(5,6)
  rrect30% 0.7x1 smd mask+0.064: 54(-2.4,-5.95) 55(-1.2,-5.95) 56(0,-5.95) 57(1.2,-5.95) 58(2.4,-5.95) 68(2.4,5.95) 69(1.2,5.95) 70(0,5.95) 71(-1.2,5.95) 72(-2.4,5.95) 101(-3.6,-5.95) 102(3.6,-5.95) 105(3.6,5.95) 106(-3.6,5.95) 107(-1.2,-4.2) 108(0,-4.2) 109(1.2,-4.2)
  rrect20% 1.3x1.3 smd mask+0.064: 89(-0.9,1.8) 90(-0.9,0) 91(-0.9,-1.8) 92(0.9,-1.8) 93(0.9,0) 94(0.9,1.8)
  silkscreen extent -8.53,-9 8.05,9
SIM-MUP-C7801 [mm]
  rect 0.58x2.1 smd: 0(-6.5,5.258) 0(-6.5,-6.742) 0(6.5,-6.742) 0(6.5,5.258)
  rect 1.8x1.5 on Mech2: 0(-3.82,-6.392) 0(-1.28,-6.392) 0(1.26,-6.392)
  rect 1x1.6 on Mech2: 0(-3.82,0.908) 0(-1.28,0.908) 0(1.26,0.908)
  rect 1.2x1.6 on Mech2: 0(1.26,4.608)
  rect 0.7x1.13 smd: 1(0.25,6.743) 2(-2.29,6.743) 5(1.52,6.743) 6(-1.02,6.743) 7(-3.56,6.743)
  rect 0.75x1.13 smd: 3(-4.83,6.743)
  rect 0.65x1.13 smd: CD(2.47,6.743)
  silkscreen extent -6.1,-11.59 6.1,6.01, body extent -6.54,-7.75 6.55,6.8, height 1.5
SMD-1.5-2P [mm]
  rect 1.5x2.3 smd paste+0: 0(-2.8,-2.425) 0(2.8,-2.425)
  rect 0.7x2.9 smd paste+0: 1(-0.75,2.125) 2(0.75,2.125)
  silkscreen extent -3.85,-3.85 3.85,3.9
SMD-1.5-3P [mm]
  rect 1.5x2.3 smd paste+0: 0(-3.55,-2.425) 0(3.55,-2.425)
  rect 0.7x2.9 smd paste+0: 1(-1.5,2.125) 2(0,2.125) 3(1.5,2.125)
  silkscreen extent -4.6,-3.85 4.6,3.9, body extent -3.75,-3.95 3.75,2.55, height 3.73
SMD-1.25-2P [mm]
  rect 2.1x3.1 smd: 0(-3.175,-1.45) 0(3.175,-1.45)
  rect 0.8x1.7 smd: 1(-0.625,1.45) 2(0.625,1.45)
  silkscreen extent -4.46,-3.55 4.48,2.59, body extent -3.62,-3.6 3.63,1.81, height 3.45
SMD-1.25-6P [mm]
  rect 2.1x3.1 smd: 0(-5.675,0) 0(5.675,0)
  rect 0.8x1.7 smd: 1(-3.125,2.9) 2(-1.875,2.9) 3(-0.625,2.9) 4(0.625,2.9) 5(1.875,2.9) 6(3.125,2.9)
  silkscreen extent -6.96,-2.1 6.98,4.04, body extent -6.12,-2.1 6.12,3.31, height 3.45
SOD-123-FL [mm] "焊盘宽度0.9-1.1"
  rect 1.2x1.2 smd: A(1.7,0) K(-1.7,0)
  silkscreen extent -1.57,-1 1.5,1, body extent -1.8,-0.83 1.8,0.82, height 0.95
SOD-523 [mm]
  rect 0.6x0.4 smd: A(0.75,0) K(-0.75,0)
  silkscreen extent -0.7,-0.43 0.63,0.43, body extent -0.8,-0.4 0.8,0.4, height 0.7
SOP-8(1.27) [mm] "5*6"
  rect 0.55x1.7 smd: 1(-1.905,-2.8)
  oval 0.55x1.7 smd: 2(-0.635,-2.8) 3(0.635,-2.8) 4(1.905,-2.8) 5(1.905,2.8) 6(0.635,2.8) 7(-0.635,2.8) 8(-1.905,2.8)
  round 0.5 on Mech15 mask+0.3: ""(-1.92,-2.56)
  silkscreen extent -2.9,-2.88 2.54,1.8, body extent -2.53,-3.13 2.53,3.13, height 1.76
SOP-8(1.27)-GND [mm] "5*6"
  rect 3.5x2.6 smd: 0(0.01,0)
  rect 0.55x1.7 smd: 1(-1.905,-2.8)
  oval 0.55x1.7 smd: 2(-0.635,-2.8) 3(0.635,-2.8) 4(1.905,-2.8) 5(1.905,2.8) 6(0.635,2.8) 7(-0.635,2.8) 8(-1.905,2.8)
  round 0.5 on Mech15 mask+0.3: ""(-1.92,-2.553)
  silkscreen extent -2.9,-2.88 2.54,1.8, body extent -2.52,-3.13 2.54,3.13, height 1.76
SOT-23-3G [mm]
  rect 1x0.8 smd: D(-1.05,0) G(1.05,-0.95) S(1.05,0.95)
  rect 0.55x0.5 on Mech1: ""(-1.025,0) ""(1.025,0.95) ""(1.025,-0.95)
  silkscreen extent -1.19,-1.77 1.25,1.77, body extent -1.41,-1.45 1.41,1.45, height 1.22
SOT-23-5P [mm]
  rect 1.1x0.508 smd: 1(1.35,-0.95) 2(1.35,0) 3(1.35,0.95) 4(-1.35,0.95) 5(-1.35,-0.95)
  silkscreen extent -1.3,-1.81 2.06,1.79, body extent -1.5,-1.5 1.5,1.5, height 1.3
SOT-323-3G [mm]
  rect 0.6x0.5 smd: D(-0.925,0) G(0.925,-0.65) S(0.925,0.65)
  rect 0.3x0.4 on Mech1: ""(-0.93,0) ""(0.93,0.65) ""(0.93,-0.65)
  round 0.15 on Mech1: ""(0,0) ""(0,0)
  silkscreen extent -0.84,-1.15 0.48,1.15, body extent -1.08,-1 1.08,1, height 0.9
SOT-323-5 [mm]
  rect 0.8x0.4 smd mask+0.051: 1(1,-0.65) 2(1,0) 3(1,0.65) 4(-1,0.65) 5(-1,-0.65)
  silkscreen extent -0.6,-1.43 1.55,1.1, body extent -1.2,-1.1 1.2,1.1, height 1.1
SOT-723-3G [mm]
  rect 0.4x0.4 smd: D(-0.5,0) G(0.5,-0.4) S(0.5,0.4)
  silkscreen extent -0.52,-0.65 0.07,0.65, body extent -0.5,-0.63 0.55,0.63, height 0.45
SSOP-24(0.635) [mm]
  rect 0.35x1.5 smd: 1(-3.492,-3)
  oval 0.35x1.5 smd: 2(-2.857,-3) 3(-2.222,-3) 4(-1.587,-3) 5(-0.952,-3) 6(-0.317,-3) 7(0.318,-3) 8(0.953,-3) 9(1.588,-3) 10(2.223,-3) 11(2.858,-3) 12(3.492,-3) 13(3.492,3) 14(2.857,3) 15(2.222,3) 16(1.587,3) 17(0.952,3) 18(0.317,3) 19(-0.318,3) 20(-0.953,3) 21(-1.588,3) 22(-2.223,3) 23(-2.858,3) 24(-3.492,3)
  round 0.4 on Mech15: ""(-3.492,-3)
  silkscreen extent -4.39,-3.44 4.39,1.83, body extent -4.35,-3 4.35,3, height 1.7
SW-4.2X3.2-4P-S [mm]
  rect 1.2x0.65 smd mask+0.05: 1(-2.075,1.075) 2(2.075,1.075) 3(-2.075,-1.075) 4(2.075,-1.075)
  silkscreen extent -2.3,-1.8 2.3,1.8, body extent -2.6,-1.68 2.6,1.67, height 2.5
SW-7.8X3.5-4P-HOLE-S-2 [mm]
  rect 0.8x1.5 smd mask+0.05: 0(-3.8,-1) 0(3.8,-1)
  round 0.9 hole 0.9: 0(-1.15,-0.4) 0(1.15,-0.4)
  rect 1.2x1.5 smd mask+0.05: 1(-2.1,1) 2(2.1,1)
  silkscreen extent -3.9,-2.4 3.9,1.1, body extent -3.9,-2.6 3.9,1.2, height 3.47
SW-18020 [mm]
  round 1.2 hole 0.8 paste-2539.97: 1(0,0)
  round 0.8 hole 0.5 paste-2539.97: 2(0,-1.3)
  silkscreen extent -2.1,-2.1 2.1,2.1
test [mm]
  round 1 smd paste-10: 1(0,0)
"TYPEC _6PIN板" [mm]
  rect 2x2 smd mask+0.064: 0(-4.77,-2.412) 0(-4.77,1.488) 0(4.77,-2.412) 0(4.77,1.488)
  rect 0.6x1.4 smd mask+0.051: A1B12(-3.2,2.413) A4B9(-2.4,2.413) B1A12(3.2,2.413) B4A9(2.4,2.413)
  rect 0.3x1.4 smd mask+0.051: A5(-1.25,2.413) A6(-0.25,2.413) A7(0.25,2.413) A8(1.25,2.413) B5(1.75,2.413) B6(0.75,2.413) B7(-0.75,2.413) B8(-1.75,2.413)
  round 0.65 hole 0.65 unplated: ""(-2.89,0.968) ""(2.89,0.968)
  silkscreen extent -4.67,-5.09 4.67,3.3, body extent -4.5,-4.93 4.5,2.47, height 3.16
UDFN2(1610) [mm]
  rect 0.58x1 smd mask+0.076: A(0.56,0) K(-0.56,0)
  rect 0.4x0.88 on Mech1: ""(-0.55,0) ""(0.55,0)
  silkscreen extent -1.15,-0.7 1.05,0.7, body extent -0.8,-0.5 0.8,0.5, height 0.59
"White oil-6X6" [mm] "二维码白油块"
  round 0.3 on Mech1: 29(0,0)
  silkscreen extent -3,-3 3,3

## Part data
ANT100: library part 1416000325, "DC-6GHz"
C100 C101 C110 C112 C113 C115 C116 C301 C303 C305 C306: library part 1405002136, "1uF/6.3V/20%/X5R"
C102: library part 1405000173, "220uF/6.3V/10%/1.2Ω"
C103 C106 C111 C218: library part 1405001308, "10uF/10V/20%/X5R"
C104 C117 C118 C203 C213 C215: library part 1405001272, "0.1uF/10V/10%/X5R"
C105 C107 C108 C109 C307 C308: library part 1405002411, "33pF/50V/5%/C0G"
C114: library part 1405001481, "10nF/16V/10%/X7R"
C200 C201: library part 1405005412, "22nF/10V/10%/X5R"
C202 C204 C206 C207 C208 C209 C210 C211 C216 C217: library part 1405005056, "1uF/10V/20%/X5R"
C205 C212: library part 1405001346, "22uF/10V/20%/X5R"
C300: library part 1405000484, "4.7uF/6.3V/20%/X5R"
C302 C304: library part 1405000392, "0.1uF/50V/10%/X7R"
CON100: library part 1416003448, "USB Type-C"
CON101: library part 1416001211, "1.25mm/3PIN"
CON102: library part 1416003211, "Push-Push NANO-SIM Card Connector"
CON200 CON201: library part 1416003013, "1.25mm/2PIN"
CON300 CON301: library part 1416000208, "1.25mm/6PIN"
CON302: library part 1416003026, "0.5mm/16PIN"
D100 D106 D300 D301 D302 D303 D304 D305: library part 1409004149, "1通道"
D101 D102: library part 1409004148, "1通道"
D103: library part 1409004319, "1通道"
D104: library part 1409001001, "1000V/1A"
D105: library part 1409003028, "1通道/4.5V/12V/2160W/600pF"
D200: library part 1409003171, "100V/300mA/4ns"
K100: library part 1414000145, "3*6*3.5"
K101: library part 1414000735, "4.2*3.2*2.5mm"
K300: library part SW-18020-TM振动开关-A2, "震动开关"
LED300: library part WS2812B
LED301: library part 1409000426, "红/25mA/54mcd"
LED302: library part 1409000351, "绿/25mA/112-285mcd"
MIC200: library part 1406000111, "-22dB/±3dB"
Q100: library part 1412000290, "PMOS/20V/4.7A"
Q101: library part 1412002660, "PMOS/12V/1.4A"
Q102: library part 1412003327, "NMOS/20V/0.5A"
R100 R107 R110 R111 R120: library part 1408001444, "10KΩ/5%"
R101 R102 R104 R105 R112 R122 R123 R124 R202 R203 R204 R205 R206 R219 R220 R222 R300: library part 1408001443, "33Ω/5%"
R106 R108 R109 R121 R301: library part 1408005605, "5.1KΩ/1%"
R113 R114 R117 R200 R201 R207 R208 R209 R210: library part 1408001835, "47KΩ/1%"
R115: library part 1408000869, "1M/5%"
R116: library part 1408001558, "4.7KΩ/5%"
R118 R119: library part 1408005685, "100KΩ/5%"
R211 R212 R213 R214 R215 R216 R217 R218 R221 R224: library part 1408001445, "1KΩ/5%"
R302 R303: library part 1408001084, "2.2KΩ/5%"
TP100 TP101 TP102 TP103 TP104 TP105 TP106 TP107 TP200 TP201 TP202 TP203 TP204 TP300 TP301 TP302 TP303: library part MARK
U100: library part 180006-03G
U102: library part CL4056
U103: library part 1407000926, "3.3V/300mA/1.6-5.5V"
U104: library part 1409000217, "双向/7.14V/600W"
U202: library part P25Q64SLA-SUH-IR, "P25Q32SH-SSH-IR"

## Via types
v1: diameter 0.23, hole 0.1, Top Layer to Layer 1, tented both sides, 385 vias
v2: diameter 0.45, hole 0.25, Top Layer to Bottom Layer, tented both sides, 379 vias
v3: diameter 0.23, hole 0.1, Layer 2 to Bottom Layer, tented both sides, 323 vias

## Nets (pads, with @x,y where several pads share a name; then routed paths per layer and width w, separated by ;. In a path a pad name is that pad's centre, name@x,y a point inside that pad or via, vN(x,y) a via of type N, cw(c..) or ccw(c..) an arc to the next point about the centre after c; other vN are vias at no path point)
3.3V: C115.2 C215.2 C303.1 C305.1 CON302.11 LED300.4 R206.2 R207.2 R220.1 R222.2 U103.5 U202.8 | length 67.9
  Top Layer w0.3: R206.2@-40.025,16.675 -40.025,17.2 -39.375,17.85 v2(-39.325,17.85) ; R207.2@-39.4,10.225 -39.4,9.725 -38.95,9.275 v2(-37.4,9.275) ; C215.2@-18.775,7.1 -17.075,7.1 -16.85,7.325 -16.85,11.05 R222.2@-16.85,11.2 ; R222.2@-16.85,11.275 -16.85,12.655 U202.8@-16.895,12.7 -16.817,12.778 -16.817,13.36 -16.253,13.925 R220.1@-15.875,13.925
  Layer 1 w0.4: v2(-37.4,3.8) -36.125,2.525 -23.7,2.525 -23.05,1.875 -18.575,1.875 -17.825,2.625 v1(-17.825,7.125)
  Layer 2 w0.3: v3(-35.975,16.525) v3(-33.25,16.525) ; v2(-17.825,3) -16.425,3 v3(-16.15,3.275)
  Bottom Layer w0.3: v3(-33.25,16.525) -33.25,17.05 -30.949,19.351 -30.949,20.049 -31.2,20.3 C305.1@-31.2,20.563 CON302.11@-31.2,21.712 ; C303.1@-16.15,3.15 -16.15,2.409 -15.8,2.058 LED300.4@-15.65,2.058
  Bottom Layer w0.4: v2(-39.325,17.85) -37.3,17.85 v3(-35.975,16.525) ; v2(-37.4,3.8) v2(-37.4,9.275) -37.4,11.025 -35.986,12.439 v3@-35.986,16.5
ADC_Li: C112.2 R113.1 R114.2 U101.96 | length 6.1
  Bottom Layer w0.15: U101.96@-24.35,19.575 -24.418,19.643 -24.418,22.238 -23.237,23.419 -23.237,23.862 C112.2@-23.25,23.875 ; R113.1@-23.875,24.475 -23.85,24.5 -23.275,24.5 R114.2@-23.25,24.525 -23.263,24.513 C112.2@-23.263,23.888
AGND: C207.1 C209.2 C210.2 C211.2 C216.1 C217.2 R218.1 R224.2 U200.17 | length 1.7
  Top Layer w0.3: C216.1@-48.429,10.646 C210.2@-48.429,12.346
  other v1: -48.9,7.575 -50.5,7.6 -47.4,7.8 -49.825,8.196 -49,8.375 -50.025,9.275 -47.6,9.275 -44.35,9.35 -45.6,9.375 -46.75,9.875 -50.5,10.25 -45.2,10.55 -44.35,10.6 -45.425,11.325 -44.35,11.45 -50.325,11.475 -44.625,12.425 -50.075,12.5 -45.675,12.525 -45.575,13.4 -44.25,13.575 -50.075,14.25 -45.875,14.425 -44.925,14.55 -50.425,14.85 -47.65,14.875 -49.325,14.883 -47.125,14.9 -46.7,14.9 -44.25,14.975 -45.775,15.45 -44.75,15.75 -44.35,16.625 -50.45,16.925 -44.4,17.3 -48.475,17.35 -47.2,18.025 -44.425,18.075 -50.475,18.15 -47.975,18.25 -49.475,18.275 -43.3,18.275 -42.3,18.275 -47.775,18.6 -48.65,18.9 -50.475,19.3 -44.15,19.375 -42.25,19.525 -41.125,19.675 -44.85,19.725 -43.225,19.775 -46.125,19.875 -49.05,20.1 -49.75,20.175 -42.3,20.651 -50.45,21.15 -48.975,21.225 -43.95,21.275 -41.3,21.725 -42.625,22.05 -41.55,22.95 -45.775,23.1 -46.9,23.225 -45.9,24.25 -46.85,24.375 -41.625,24.4 -43.95,25.35 -45.55,25.4 -42.425,25.4 -41.075,25.6 -47.475,25.65 -49.975,26.375 -46.15,26.65 -44.125,26.7 -48.3,26.725 -42.275,26.775
  other v2: -48.4,11.45 -48.475,14.925 -50.1,16.125 -48.6,18.125
AUD_N: C200.1 C217.1 R216.1 | length 19.6
  Top Layer w0.2: R216.1@-49.55,13.125 -49.55,9.834 -48.038,8.322 -36.303,8.322 -34.787,9.838 -34.787,10.138 C200.1@-34.775,10.15
AUD_P: C201.1 C216.2 R215.2 | length 16.3
  Top Layer w0.2: C216.2@-48.979,10.646 -48.979,9.798 -47.881,8.7 -36.46,8.7 -35.329,9.83 -35.329,10.1 -35.325,10.104 C201.1@-35.325,10.15 ; C216.2@-48.975,10.65 R215.2@-48.975,11.225
CHG_LED: LED301.K R100.2 U102.7 | length 23.3
  Top Layer w0.2: v2(-32.325,19.901) v2@-32.352,19.901 ; R100.2@-31.925,20.525 -32.175,20.525 -32.352,20.348 v2@-32.352,19.901 ; U102.7@-31.885,17.775 -31.885,19.134 -32.352,19.601 v2@-32.352,19.901
  Bottom Layer w0.2: LED301.K@-35.7,1.3 -35.7,1.95 -35.7,2.113 -35.712,2.126 -35.712,4.518 -35.339,4.891 -35.339,11.437 -34.2,12.576 -34.2,18.026 v2(-32.325,19.901)
CHG_STATE: R100.1 U101.58 | length 11.2
  Top Layer w0.15: R100.1@-31.35,20.525 -29.128,20.525 -28.976,20.677 v2(-28.895,20.677)
  Layer 2 w0.15: v2(-28.895,20.677) -28.838,20.735 -28.692,20.735 -28.657,20.77 -26.264,20.77 -22.844,17.35 -22.628,17.133 -22.628,17.01 v3(-22.612,16.994)
  Bottom Layer w0.15: v3(-22.612,16.994) -22.597,16.979 -22.597,16.748 -22.324,16.475 U101.58@-22.2,16.475
FLASH_CLK: R112.2 U202.6 | length 1.5
  Top Layer w0.2: U202.6@-19.435,12.7 -19.43,12.695 -19.43,11.18 R112.2@-19.425,11.175
FLASH_CS: U101.64 U202.1 | length 2.9
  Top Layer w0.2: U202.1@-16.895,17.775 U202.1@-16.895,18.3 -16.743,18.148 v2(-16.198,18.148)
  Bottom Layer w0.2: v2(-16.198,18.148) -16.15,18.196 -15.911,18.196 -15.268,18.839 U101.64@-15.041,18.839 ; U101.64@-15.05,18.928 U101.64@-15.05,19.057
FLASH_MISO: R219.1 U101.62 | length 1.2
  Top Layer w0.2: R219.1@-17.513,20.238 -17.489,20.215 -17.489,19.84 v2(-17.466,19.817)
  Bottom Layer w0.2: v2(-17.466,19.817) -17.458,19.809 -17.458,19.083 U101.62@-17.45,19.075
FLASH_MOSI: R104.2 U202.5 | length 14
  Top Layer w0.2: U202.5@-20.705,12.7 -20.709,12.704 -20.709,14.409 -22.477,16.177 -22.477,20.398 -21.179,21.696 -18.371,21.696 -18.078,21.403 R104.2@-18.078,20.903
